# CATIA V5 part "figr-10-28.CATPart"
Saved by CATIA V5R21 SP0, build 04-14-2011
Part number: Part1
Bounding box of the stored display mesh (mm): x -60 to 70, y 0 to 100.393, z 0 to 0
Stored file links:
  D:\CATIA V5R21 E-RESOURCES\CATIA-V5R21\catia-v5r21-prt\c10-catia-v5r20-prt\c10-catia-v5r21-figr-10-28.CATPart
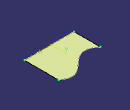
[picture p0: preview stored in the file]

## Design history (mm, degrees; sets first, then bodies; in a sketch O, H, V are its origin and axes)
Set1
  Sweep1: type Segment, GuideCrv (Sketch1; Sketch2), Length1 0, Length2 0
Body1 (main body)
  Sketch1 on xy-plane, origin (0, 0, 0), H (1, 0, 0), V (0, 1, 0)
    line L1 (-60, 0) -> (70, 0)
    point P1 (-60, 0)
    coincidence: P1 H
    horizontal: L1 H
  Sketch2 on xy-plane, origin (0, 0, 0), H (1, 0, 0), V (0, 1, 0)
    spline S1 through (-60, 70) (-20, 60) (40, 100) (70, 90)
